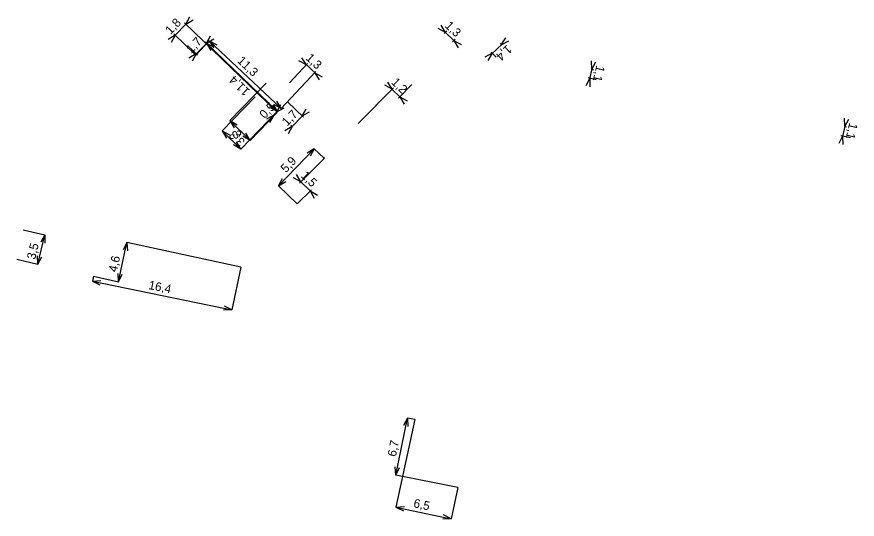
# Model space of a CAD drawing. Extents: x -743226 to -743024, y -1051383 to -1051228.
# Drawn here: x -743225.9 to -743129.5, y -1051383.1 to -1051325.4 of the extents above; entities that cross this region are included whole.
import ezdxf

# ---------------------------------------------------------------- set-up
doc = ezdxf.new("R2010")
doc.units = 0
doc.layers.add('Kota_NN', color=7, linetype='Continuous')
doc.layers.add('Kota_VN', color=7, linetype='Continuous')

msp = doc.modelspace()

# ---------------------------------------------------------------- linework, layer by layer
at = {"layer": 'Kota_NN'}
for p, q in [((-743206.512, -1051326.21), (-743206.045, -1051325.37)), ((-743206.512, -1051326.21), (-743205.688, -1051325.716)), ((-743207.875, -1051327.621), (-743206.373, -1051326.067)), ((-743196.07, -1051336.3), (-743206.655, -1051326.071)), ((-743207.736, -1051327.478), (-743208.56, -1051327.972)), ((-743207.736, -1051327.478), (-743208.203, -1051328.318)), ((-743205.37, -1051329.764), (-743207.88, -1051327.339)), ((-743205.37, -1051329.764), (-743203.82, -1051328.12)), ((-743203.82, -1051328.12), (-743195.578, -1051335.892)), ((-743203.82, -1051328.12), (-743202.975, -1051328.576)), ((-743203.82, -1051328.12), (-743203.316, -1051328.938)), ((-743192.684, -1051330.89), (-743193.53, -1051330.435)), ((-743192.684, -1051330.89), (-743193.189, -1051330.073)), ((-743194.626, -1051332.954), (-743192.547, -1051330.744)), ((-743192.829, -1051330.753), (-743191.573, -1051331.935)), ((-743192.21, -1051332.32), (-743195.578, -1051335.892)), ((-743192.21, -1051332.32), (-743191.582, -1051331.652)), ((-743191.719, -1051331.798), (-743190.873, -1051332.253)), ((-743191.719, -1051331.798), (-743191.214, -1051332.615)), ((-743182.839, -1051333.693), (-743183.674, -1051333.218)), ((-743182.839, -1051333.693), (-743183.325, -1051332.864)), ((-743180.564, -1051333.152), (-743182.096, -1051334.706)), ((-743186.73, -1051337.64), (-743182.698, -1051333.551)), ((-743182.981, -1051333.553), (-743181.813, -1051334.704)), ((-743198.568, -1051334.565), (-743202.349, -1051338.478)), ((-743195.578, -1051335.892), (-743196.082, -1051335.074)), ((-743181.956, -1051334.564), (-743181.121, -1051335.039)), ((-743181.956, -1051334.564), (-743181.47, -1051335.393)), ((-743196.07, -1051336.3), (-743200.189, -1051340.564)), ((-743196.567, -1051336.804), (-743195.93, -1051336.158)), ((-743195.578, -1051335.892), (-743196.423, -1051335.436)), ((-743196.07, -1051336.3), (-743195.595, -1051335.465)), ((-743196.07, -1051336.3), (-743195.241, -1051335.814)), ((-743196.07, -1051336.3), (-743196.07, -1051336.3)), ((-743196.426, -1051336.661), (-743197.255, -1051337.147)), ((-743196.426, -1051336.661), (-743196.901, -1051337.496)), ((-743196.426, -1051336.661), (-743196.426, -1051336.661)), ((-743202.349, -1051338.478), (-743200.189, -1051340.564)), ((-743202.349, -1051338.478), (-743201.509, -1051338.944)), ((-743202.349, -1051338.478), (-743201.855, -1051339.302)), ((-743200.189, -1051340.564), (-743201.029, -1051340.098)), ((-743200.189, -1051340.564), (-743200.683, -1051339.74)), ((-743195.865, -1051344.805), (-743191.77, -1051340.536)), ((-743191.77, -1051340.536), (-743192.592, -1051341.033)), ((-743191.77, -1051340.536), (-743192.233, -1051341.377)), ((-743190.63, -1051341.63), (-743191.77, -1051340.536)), ((-743190.57, -1051341.56), (-743193.451, -1051344.472)), ((-743195.865, -1051344.805), (-743195.402, -1051343.964)), ((-743193.31, -1051344.329), (-743194.144, -1051343.853)), ((-743193.31, -1051344.329), (-743193.795, -1051343.499)), ((-743195.865, -1051344.805), (-743195.043, -1051344.308)), ((-743193.721, -1051346.862), (-743195.865, -1051344.805)), ((-743193.452, -1051344.189), (-743192.109, -1051345.518)), ((-743193.721, -1051346.862), (-743192.111, -1051345.235)), ((-743192.252, -1051345.377), (-743191.418, -1051345.853)), ((-743192.252, -1051345.377), (-743191.767, -1051346.207)), ((-743225.183, -1051349.851), (-743222.716, -1051350.437)), ((-743223.514, -1051353.797), (-743222.716, -1051350.437)), ((-743222.716, -1051350.437), (-743223.173, -1051351.282)), ((-743222.716, -1051350.437), (-743222.689, -1051351.397)), ((-743214.251, -1051355.806), (-743213.273, -1051351.306)), ((-743213.273, -1051351.306), (-743213.713, -1051352.16)), ((-743200.215, -1051354.144), (-743213.273, -1051351.306)), ((-743213.273, -1051351.306), (-743213.228, -1051352.266)), ((-743225.915, -1051353.226), (-743223.514, -1051353.797)), ((-743223.514, -1051353.797), (-743223.541, -1051352.837)), ((-743223.514, -1051353.797), (-743223.057, -1051352.952)), ((-743200.215, -1051354.144), (-743201.221, -1051359.029)), ((-743217.13, -1051355.18), (-743217.243, -1051355.728)), ((-743217.243, -1051355.728), (-743216.284, -1051355.672)), ((-743217.13, -1051355.18), (-743214.251, -1051355.806)), ((-743214.251, -1051355.806), (-743214.296, -1051354.846)), ((-743214.251, -1051355.806), (-743213.811, -1051354.952)), ((-743217.243, -1051355.728), (-743201.221, -1051359.029)), ((-743217.243, -1051355.728), (-743216.384, -1051356.159)), ((-743201.221, -1051359.029), (-743202.18, -1051359.085)), ((-743201.221, -1051359.029), (-743202.08, -1051358.598)), ((-743182.419, -1051378.015), (-743181.088, -1051371.465)), ((-743180.239, -1051371.638), (-743182.394, -1051381.691)), ((-743181.088, -1051371.465), (-743181.517, -1051372.325)), ((-743180.239, -1051371.638), (-743181.088, -1051371.465)), ((-743181.088, -1051371.465), (-743181.03, -1051372.424)), ((-743182.419, -1051378.015), (-743182.477, -1051377.056)), ((-743182.419, -1051378.015), (-743181.99, -1051377.155)), ((-743175.31, -1051379.46), (-743182.419, -1051378.015)), ((-743175.31, -1051379.46), (-743176.078, -1051383.044)), ((-743182.394, -1051381.691), (-743181.435, -1051381.643)), ((-743182.394, -1051381.691), (-743176.078, -1051383.044)), ((-743182.394, -1051381.691), (-743181.539, -1051382.129)), ((-743176.078, -1051383.044), (-743176.933, -1051382.606)), ((-743176.078, -1051383.044), (-743177.037, -1051383.092))]:
    msp.add_line(p, q, dxfattribs=at)
at = {"layer": 'Kota_VN'}
for p, q in [((-743176.727, -1051327.163), (-743177.568, -1051326.699)), ((-743176.727, -1051327.163), (-743177.224, -1051326.341)), ((-743204.136, -1051328.411), (-743203.666, -1051327.573)), ((-743176.871, -1051327.025), (-743175.61, -1051328.236)), ((-743176.572, -1051327.002), (-743176.865, -1051327.307)), ((-743205.472, -1051329.783), (-743203.996, -1051328.268)), ((-743204.135, -1051328.412), (-743204.279, -1051328.271)), ((-743204.136, -1051328.4), (-743204.143, -1051328.407)), ((-743195.966, -1051336.294), (-743204.143, -1051328.407)), ((-743204.143, -1051328.407), (-743203.303, -1051328.873)), ((-743204.143, -1051328.407), (-743203.648, -1051329.23)), ((-743204.136, -1051328.411), (-743203.31, -1051327.92)), ((-743175.599, -1051327.937), (-743175.893, -1051328.242)), ((-743175.754, -1051328.098), (-743174.913, -1051328.562)), ((-743175.754, -1051328.098), (-743175.257, -1051328.92)), ((-743170.163, -1051328.461), (-743171.487, -1051329.699)), ((-743170.302, -1051328.605), (-743170.445, -1051328.452)), ((-743170.309, -1051328.598), (-743169.8, -1051327.783)), ((-743170.309, -1051328.598), (-743169.461, -1051328.146)), ((-743205.332, -1051329.639), (-743206.158, -1051330.13)), ((-743205.959, -1051329.029), (-743205.189, -1051329.779)), ((-743205.332, -1051329.639), (-743205.802, -1051330.477)), ((-743171.341, -1051329.562), (-743172.189, -1051330.014)), ((-743171.341, -1051329.562), (-743171.85, -1051330.377)), ((-743170.916, -1051330.017), (-743171.477, -1051329.416)), ((-743159.916, -1051331.408), (-743159.946, -1051330.448)), ((-743159.916, -1051331.408), (-743159.462, -1051330.561)), ((-743159.871, -1051331.213), (-743160.204, -1051332.635)), ((-743159.926, -1051331.405), (-743159.722, -1051331.453)), ((-743160.158, -1051332.44), (-743160.612, -1051333.287)), ((-743159.408, -1051332.616), (-743160.353, -1051332.395)), ((-743160.158, -1051332.44), (-743160.128, -1051333.4)), ((-743197.286, -1051332.985), (-743201.478, -1051337.296)), ((-743194.865, -1051335.127), (-743193.013, -1051336.906)), ((-743196.02, -1051336.35), (-743199.145, -1051339.564)), ((-743195.966, -1051336.294), (-743196.806, -1051335.828)), ((-743195.966, -1051336.294), (-743196.461, -1051335.471)), ((-743195.955, -1051336.283), (-743195.966, -1051336.294)), ((-743193.157, -1051336.768), (-743192.693, -1051335.927)), ((-743193.157, -1051336.768), (-743192.334, -1051336.271)), ((-743199.145, -1051339.564), (-743201.478, -1051337.296)), ((-743201.478, -1051337.296), (-743200.64, -1051337.765)), ((-743201.478, -1051337.296), (-743200.986, -1051338.121)), ((-743194.456, -1051338.12), (-743193.019, -1051336.624)), ((-743130.882, -1051337.987), (-743130.916, -1051337.027)), ((-743130.882, -1051337.987), (-743130.431, -1051337.138)), ((-743194.318, -1051337.976), (-743195.141, -1051338.473)), ((-743194.318, -1051337.976), (-743194.782, -1051338.817)), ((-743194.311, -1051337.983), (-743194.462, -1051337.837)), ((-743130.837, -1051337.792), (-743131.177, -1051339.27)), ((-743130.892, -1051337.984), (-743130.687, -1051338.031)), ((-743199.145, -1051339.564), (-743199.983, -1051339.095)), ((-743199.145, -1051339.564), (-743199.637, -1051338.739)), ((-743131.132, -1051339.075), (-743131.583, -1051339.924)), ((-743130.229, -1051339.283), (-743131.327, -1051339.03)), ((-743131.132, -1051339.075), (-743131.098, -1051340.035))]:
    msp.add_line(p, q, dxfattribs=at)

# ---------------------------------------------------------------- texts
at = {"layer": 'Kota_NN'}
for s, rotation, p in [('1,8', 45.98214, (-743208.273, -1051327.458)), ('11,3', 316.68415, (-743200.688, -1051330.524)), ('1,3', 316.74075, (-743192.83, -1051330.203)), ('1,2', 315.40742, (-743182.999, -1051332.973)), ('0,5', 45.38362, (-743197.465, -1051337.144)), ('3', 315.98791, (-743201.232, -1051339)), ('5,9', 46.19432, (-743195.025, -1051343.352)), ('1,5', 315.30541, (-743193.382, -1051343.697)), ('3,5', 76.63766, (-743223.811, -1051353.315)), ('4,6', 77.73715, (-743214.435, -1051354.767)), ('16,4', 348.35784, (-743210.852, -1051356.637)), ('6,7', 78.5106, (-743182.41, -1051375.961)), ('6,5', 347.90119, (-743180.449, -1051381.698))]:
    msp.add_text(s, height=1, rotation=rotation, dxfattribs=at).set_placement(p)
at = {"layer": 'Kota_VN'}
for s, rotation, p in [('1,3', 316.1471, (-743176.857, -1051326.483)), ('1,7', 45.74605, (-743205.886, -1051329.634)), ('1,4', 223.06152, (-743169.646, -1051328.525)), ('1,1', 256.80939, (-743159.384, -1051330.888)), ('11,4', 136.03175, (-743199.082, -1051333.844)), ('1,7', 46.14404, (-743194.885, -1051337.989)), ('1,1', 257.05211, (-743130.358, -1051337.493)), ('3,3', 135.80023, (-743199.639, -1051339.641))]:
    msp.add_text(s, height=1, rotation=rotation, dxfattribs=at).set_placement(p)

doc.saveas('drawing.dxf')
